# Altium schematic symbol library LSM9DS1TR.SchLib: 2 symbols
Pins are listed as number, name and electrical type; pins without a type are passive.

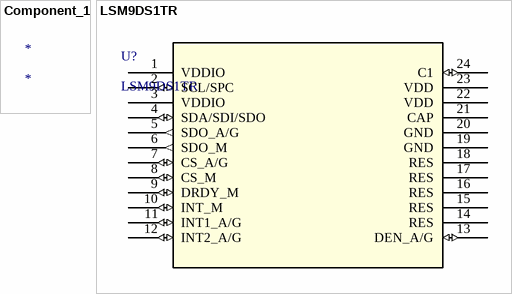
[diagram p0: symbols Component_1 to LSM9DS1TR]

## Component_1
designator *

## LSM9DS1TR
designator U?
No Description Available; Vendor: STMicroelectronics; Built_By: EMA_Jessica; SourceLibrary: Updates_to_database_2020-11-03
footprint LGA-24_3X3P5X1_STM
pins: 1 VDDIO (power), 2 SCL/SPC (io), 3 VDDIO (power), 4 SDA/SDI/SDO (io), 5 SDO_A/G (out), 6 SDO_M (out), 7 CS_A/G (io), 8 CS_M (io), 9 DRDY_M (io), 10 INT_M (io), 11 INT1_A/G (io), 12 INT2_A/G (io), 13 DEN_A/G (io), 14 RES, 15 RES, 16 RES, 17 RES, 18 RES, 19 GND (power), 20 GND (power), 21 CAP, 22 VDD (power), 23 VDD (power), 24 C1 (io)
